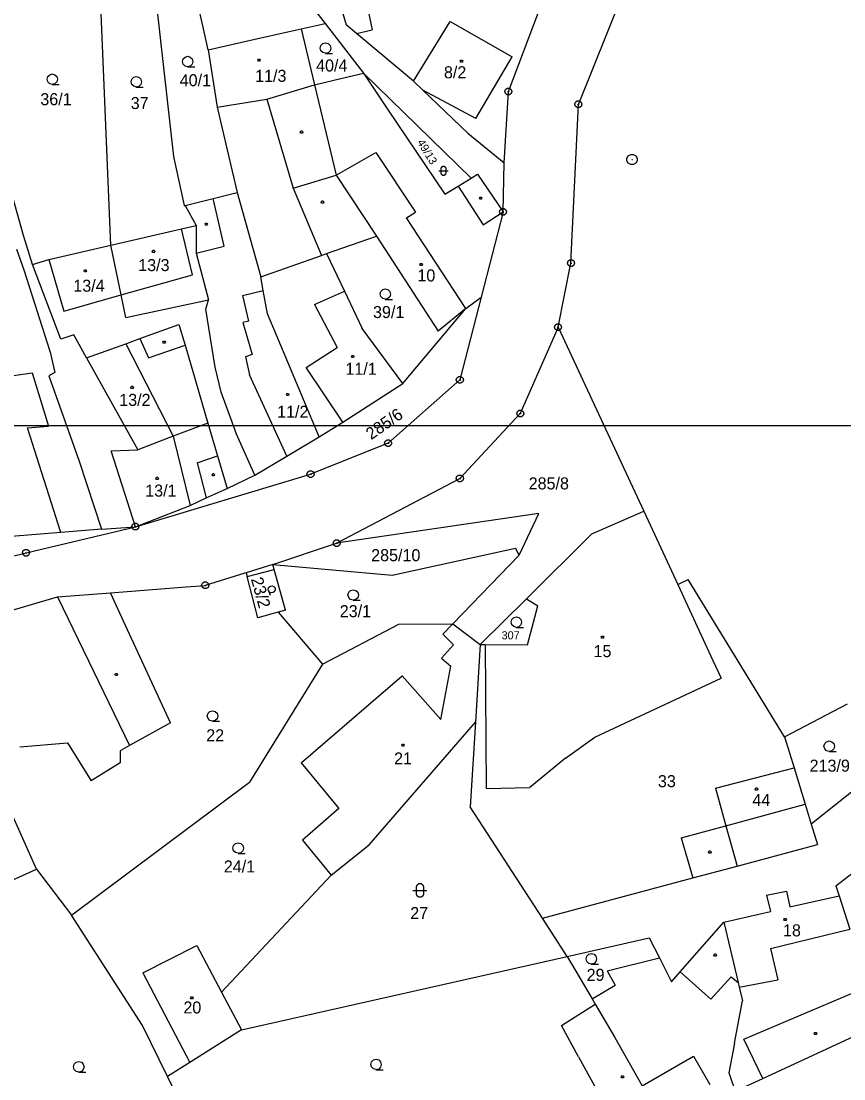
# Model space of a CAD drawing. Extents: x -780000 to -777378, y -1011169 to -1009297.
# Drawn here: x -779102.6 to -778986.4, y -1010360.1 to -1010210.7 of the extents above; entities that cross this region are included whole.
import ezdxf

# ---------------------------------------------------------------- set-up
doc = ezdxf.new("R2010")
doc.units = 0
for name, color, linetype in [('Default', 7, 'Continuous'), ('KN_HRANICE', 7, 'Continuous'), ('KN_KULTURY', 7, 'Continuous'), ('KN_PARCELY', 7, 'Continuous'), ('KN_SLUCKY', 7, 'Continuous'), ('LEGENDA', 7, 'Continuous')]:
    doc.layers.add(name, color=color, linetype=linetype)

# ---------------------------------------------------------------- blocks, each defined once
blk = doc.blocks.new('101')
at = {"layer": 'Default'}
blk.add_line((-0.05, 0), (0.05, 0), dxfattribs=at)
blk.add_lwpolyline([(0.19, 0.72), (0.53, 0.53), (0.72, 0.19), (0.72, -0.2), (0.53, -0.54), (0.19, -0.73), (-0.2, -0.73), (-0.54, -0.54), (-0.73, -0.2), (-0.73, 0.19), (-0.54, 0.53), (-0.2, 0.72), (0.19, 0.72)], dxfattribs=at)
blk = doc.blocks.new('304')
at = {"layer": 'Default'}
blk.add_lwpolyline([(0, 0), (-0.38, 0.1), (-0.65, 0.37), (-0.75, 0.74), (-0.65, 1.11), (-0.38, 1.38), (-0.01, 1.48), (0.36, 1.38), (0.63, 1.11), (0.73, 0.73), (0.63, 0.35), (0.36, 0.08), (-0.02, -0.02), (0.98, -0.02)], dxfattribs=at)
blk = doc.blocks.new('316')
at = {"layer": 'Default'}
for points in [[(-0.5, 1.5), (-0.4, 1.79), (-0.15, 1.97), (0.16, 1.97), (0.41, 1.79), (0.51, 1.5), (0.51, 0.5), (0.41, 0.21), (0.16, 0.03), (-0.15, 0.03), (-0.4, 0.21), (-0.5, 0.5), (-0.5, 1.5)], [(-1, 1), (0.27, 1), (1, 1)]]:
    blk.add_lwpolyline(points, dxfattribs=at)
blk = doc.blocks.new('NAHRADNI_SYMBOL')
at = {"layer": 'Default'}
blk.add_lwpolyline([(0.09, 0.15), (0.18, 0), (0.09, -0.15), (-0.09, -0.15), (-0.18, 0), (-0.09, 0.15), (0.09, 0.15)], dxfattribs=at)
blk = doc.blocks.new('402')
at = {"layer": 'Default'}
blk.add_lwpolyline([(0.09, 0.15), (0.18, 0), (0.09, -0.15), (-0.09, -0.15), (-0.18, 0), (-0.09, 0.15), (0.09, 0.15)], dxfattribs=at)
blk = doc.blocks.new('105')
at = {"layer": 'Default'}
blk.add_line((-0.12, 0), (0.12, 0), dxfattribs=at)
blk.add_lwpolyline([(0.15, 0.48), (0.4, 0.3), (0.5, 0.01), (0.4, -0.28), (0.15, -0.46), (-0.16, -0.46), (-0.41, -0.28), (-0.51, 0.01), (-0.41, 0.3), (-0.16, 0.48), (0.15, 0.48)], dxfattribs=at)

msp = doc.modelspace()

# ---------------------------------------------------------------- linework, layer by layer
at = {"layer": 'KN_HRANICE'}
for p, q in [((-779089.99, -1010242.37), (-779091.64, -1010201.91)), ((-779076.2, -1010214.76), (-779078.76, -1010203.29)), ((-779023.92, -1010222.47), (-779017.34, -1010206.13)), ((-779062.19, -1010207.85), (-779059.7, -1010211.07)), ((-779057.43, -1010208.85), (-779056.71, -1010211.24)), ((-779033.8, -1010220.65), (-779029.4, -1010209.06)), ((-779069.82, -1010213.33), (-779064.77, -1010212.2)), ((-779064.77, -1010212.2), (-779063.08, -1010211.82)), ((-779063.08, -1010211.82), (-779059.7, -1010211.07)), ((-779063.08, -1010211.82), (-779061.2, -1010219.69)), ((-779059.7, -1010211.07), (-779054.29, -1010218.08)), ((-779055.26, -1010212.45), (-779056.71, -1010211.24)), ((-779076.2, -1010214.76), (-779069.82, -1010213.33)), ((-779047.2, -1010219.18), (-779055.26, -1010212.45)), ((-779076.2, -1010214.76), (-779074.94, -1010222.88)), ((-779057.29, -1010218.78), (-779054.29, -1010218.08)), ((-779054.29, -1010218.08), (-779050.87, -1010223.15)), ((-779054.29, -1010218.08), (-779039.06, -1010232.9)), ((-779061.2, -1010219.69), (-779057.29, -1010218.78)), ((-779061.2, -1010219.69), (-779058.14, -1010232.46)), ((-779047.2, -1010219.18), (-779045.87, -1010220.45)), ((-779045.87, -1010220.45), (-779039.55, -1010226.53)), ((-779034.42, -1010230.71), (-779033.8, -1010220.65)), ((-779024.96, -1010244.9), (-779023.92, -1010222.47)), ((-779074.94, -1010222.88), (-779072.13, -1010234.9)), ((-779050.87, -1010223.15), (-779042.77, -1010235.17)), ((-779039.55, -1010226.53), (-779034.42, -1010230.71)), ((-779102.33, -1010241), (-779105.07, -1010231.05)), ((-779034.55, -1010237.65), (-779034.42, -1010230.71)), ((-779058.14, -1010232.46), (-779052.46, -1010241.08)), ((-779040.92, -1010234.04), (-779039.06, -1010232.9)), ((-779039.06, -1010232.9), (-779038.16, -1010232.35)), ((-779038.16, -1010232.35), (-779034.55, -1010237.65)), ((-779042.77, -1010235.17), (-779040.92, -1010234.04)), ((-779079.48, -1010236.74), (-779075.52, -1010235.75)), ((-779075.52, -1010235.75), (-779072.13, -1010234.9)), ((-779072.13, -1010234.9), (-779068.8, -1010246.85)), ((-779079.62, -1010236.77), (-779079.48, -1010236.74)), ((-779079.48, -1010236.74), (-779077.92, -1010239.59)), ((-779034.55, -1010237.65), (-779037.66, -1010249.73)), ((-779089.99, -1010242.37), (-779079.97, -1010240.06)), ((-779079.97, -1010240.06), (-779077.92, -1010239.59)), ((-779077.92, -1010239.59), (-779077.92, -1010243.48)), ((-779101.02, -1010245.11), (-779102.33, -1010241)), ((-779059.5, -1010243.56), (-779052.46, -1010241.08)), ((-779052.46, -1010241.08), (-779043.73, -1010254.53)), ((-779103.32, -1010242.93), (-779102.28, -1010245.85)), ((-779098.71, -1010244.39), (-779089.99, -1010242.37)), ((-779088.5, -1010249.4), (-779089.99, -1010242.37)), ((-779077.92, -1010243.48), (-779076.18, -1010250.09)), ((-779060.22, -1010243.82), (-779059.5, -1010243.56)), ((-779059.5, -1010243.56), (-779056.98, -1010248.86)), ((-779101.02, -1010245.11), (-779098.71, -1010244.39)), ((-779097.05, -1010255.65), (-779101.02, -1010245.11)), ((-779068.8, -1010246.85), (-779060.22, -1010243.82)), ((-779026.78, -1010253.95), (-779024.96, -1010244.9)), ((-779102.28, -1010245.85), (-779098.52, -1010257.5)), ((-779068.44, -1010248.79), (-779068.8, -1010246.85)), ((-779087.83, -1010252.59), (-779088.5, -1010249.4)), ((-779067.83, -1010252.08), (-779068.44, -1010248.79)), ((-779056.98, -1010248.86), (-779054.48, -1010254.13)), ((-779037.66, -1010249.73), (-779040.66, -1010261.41)), ((-779039.84, -1010251.3), (-779037.66, -1010249.73)), ((-779087.83, -1010252.59), (-779076.18, -1010250.09)), ((-779076.54, -1010251.4), (-779076.18, -1010250.09)), ((-779075.23, -1010259.6), (-779076.54, -1010251.4)), ((-779066.56, -1010255.1), (-779067.83, -1010252.08)), ((-779048.74, -1010261.92), (-779039.84, -1010251.3)), ((-779039.84, -1010251.3), (-779043.73, -1010254.53)), ((-779085.85, -1010255.56), (-779080.36, -1010253.56)), ((-779080.36, -1010253.56), (-779079.49, -1010256.51)), ((-779048.74, -1010261.92), (-779054.48, -1010254.13)), ((-779026.78, -1010253.95), (-779032.12, -1010266.16)), ((-779026.78, -1010253.95), (-779014.69, -1010279.95)), ((-779095.21, -1010255.03), (-779097.05, -1010255.65)), ((-779093.41, -1010258.3), (-779095.21, -1010255.03)), ((-779087.87, -1010256.29), (-779085.85, -1010255.56)), ((-779060.55, -1010269.44), (-779066.56, -1010255.1)), ((-779093.41, -1010258.3), (-779087.87, -1010256.29)), ((-779079.49, -1010256.51), (-779076.26, -1010267.51)), ((-779098.52, -1010257.5), (-779097.87, -1010260.36)), ((-779093.41, -1010258.3), (-779086.17, -1010271.27)), ((-779107.93, -1010261.36), (-779101.09, -1010260.41)), ((-779101.09, -1010260.41), (-779098.76, -1010267.92)), ((-779097.87, -1010260.36), (-779098.72, -1010260.84)), ((-779098.72, -1010260.84), (-779094.46, -1010272.88)), ((-779050.79, -1010270.34), (-779040.66, -1010261.41)), ((-779057.2, -1010267.35), (-779048.74, -1010261.92)), ((-779032.12, -1010266.16), (-779040.66, -1010275.32)), ((-779076.26, -1010267.51), (-779081.16, -1010269.37)), ((-779076.26, -1010267.51), (-779074.9, -1010272.13)), ((-779060.55, -1010269.44), (-779057.2, -1010267.35)), ((-779101.73, -1010268.16), (-779098.76, -1010267.92)), ((-779097.04, -1010282.96), (-779101.73, -1010268.16)), ((-779081.16, -1010269.37), (-779086.17, -1010271.27)), ((-779065.1, -1010272.18), (-779060.55, -1010269.44)), ((-779050.79, -1010270.34), (-779061.75, -1010274.71)), ((-779089.91, -1010271.43), (-779086.17, -1010271.27)), ((-779086.5, -1010282.14), (-779089.91, -1010271.43)), ((-779074.9, -1010272.13), (-779073.55, -1010276.72)), ((-779094.46, -1010272.88), (-779091.27, -1010282.5)), ((-779069.64, -1010274.85), (-779065.1, -1010272.18)), ((-779086.5, -1010282.14), (-779061.75, -1010274.71)), ((-779073.55, -1010276.72), (-779069.64, -1010274.85)), ((-779058.07, -1010284.48), (-779040.66, -1010275.32)), ((-779078.75, -1010279.13), (-779076.48, -1010278.07)), ((-779076.48, -1010278.07), (-779073.55, -1010276.72)), ((-779086.5, -1010282.14), (-779078.75, -1010279.13)), ((-779029.51, -1010280.26), (-779058.07, -1010284.48)), ((-779032.26, -1010286.16), (-779029.51, -1010280.26)), ((-779022.02, -1010283.13), (-779014.69, -1010279.95)), ((-779014.69, -1010279.95), (-779009.89, -1010290.29)), ((-779101.94, -1010285.82), (-779086.5, -1010282.14)), ((-779091.27, -1010282.5), (-779097.04, -1010282.96)), ((-779091.27, -1010282.5), (-779086.5, -1010282.14)), ((-779022.02, -1010283.13), (-779031.26, -1010292.31)), ((-779067.08, -1010287.5), (-779058.07, -1010284.48)), ((-779050.21, -1010289), (-779032.82, -1010285.16)), ((-779032.26, -1010286.16), (-779032.82, -1010285.16)), ((-779112.94, -1010288.54), (-779101.94, -1010285.82)), ((-779041.67, -1010295.86), (-779032.26, -1010286.16)), ((-779067.08, -1010287.5), (-779070.83, -1010288.65)), ((-779066.89, -1010288.17), (-779067.08, -1010287.5)), ((-779067.08, -1010287.5), (-779050.21, -1010289)), ((-779065.31, -1010293.92), (-779066.89, -1010288.17)), ((-779071.05, -1010288.72), (-779076.63, -1010290.43)), ((-779070.83, -1010288.65), (-779071.05, -1010288.72)), ((-779070.83, -1010288.65), (-779070.69, -1010289.16)), ((-779069.19, -1010295.01), (-779070.69, -1010289.16)), ((-779009.89, -1010290.29), (-779008.43, -1010289.59)), ((-778994.79, -1010311.83), (-779008.43, -1010289.59)), ((-779097.5, -1010292.06), (-779090.04, -1010291.48)), ((-779090.04, -1010291.48), (-779079.33, -1010290.64)), ((-779087.9, -1010296.09), (-779090.04, -1010291.48)), ((-779079.33, -1010290.64), (-779076.63, -1010290.43)), ((-779009.89, -1010290.29), (-779004.9, -1010301.02)), ((-779107.13, -1010294.85), (-779097.5, -1010292.06)), ((-779031.26, -1010292.31), (-779037.78, -1010298.79)), ((-779031.26, -1010292.31), (-779029.63, -1010293.31)), ((-779066.34, -1010294.21), (-779069.19, -1010295.01)), ((-779065.31, -1010293.92), (-779066.34, -1010294.21)), ((-779066.34, -1010294.21), (-779060.06, -1010301.54)), ((-779031.09, -1010298.84), (-779029.63, -1010293.31)), ((-779060.06, -1010301.54), (-779049.3, -1010295.9)), ((-779049.3, -1010295.9), (-779041.67, -1010295.86)), ((-779043.09, -1010297.32), (-779041.67, -1010295.86)), ((-779041.67, -1010295.86), (-779037.78, -1010298.79)), ((-779081.53, -1010309.87), (-779087.9, -1010296.09)), ((-779043.09, -1010297.32), (-779041.55, -1010298.82)), ((-779043.27, -1010300.7), (-779041.55, -1010298.82)), ((-779037.78, -1010298.79), (-779038.46, -1010309.75)), ((-779037.78, -1010298.79), (-779037.1, -1010298.8)), ((-779037.1, -1010298.8), (-779031.09, -1010298.84)), ((-779037.1, -1010298.8), (-779036.94, -1010319.12)), ((-779060.06, -1010301.54), (-779070.4, -1010318.23)), ((-779043.36, -1010309.37), (-779041.95, -1010301.84)), ((-779043.27, -1010300.7), (-779041.95, -1010301.84)), ((-779004.9, -1010301.02), (-779003.74, -1010303.52)), ((-779063.1, -1010315.51), (-779048.83, -1010303.23)), ((-779043.36, -1010309.37), (-779048.83, -1010303.23)), ((-779021.61, -1010311.89), (-779003.74, -1010303.52)), ((-778994.79, -1010311.83), (-778985.9, -1010307.16)), ((-779081.53, -1010309.87), (-779087.34, -1010313.07)), ((-779053.49, -1010327.09), (-779038.46, -1010309.75)), ((-779038.46, -1010309.75), (-779039.2, -1010321.7)), ((-779025.76, -1010314.84), (-779021.61, -1010311.89)), ((-778994.79, -1010311.83), (-778993.45, -1010316.22)), ((-779102.83, -1010313.22), (-779096.1, -1010312.69)), ((-779096.1, -1010312.69), (-779092.74, -1010318.04)), ((-779087.34, -1010313.07), (-779088.67, -1010313.8)), ((-779088.67, -1010313.8), (-779088.64, -1010315.52)), ((-779025.76, -1010314.84), (-779030.77, -1010318.99)), ((-779088.64, -1010315.52), (-779092.74, -1010318.04)), ((-779063.1, -1010315.51), (-779057.77, -1010321.93)), ((-779004.53, -1010319.08), (-778993.45, -1010316.22)), ((-778993.45, -1010316.22), (-778991.89, -1010321.33)), ((-779095.54, -1010337.04), (-779070.4, -1010318.23)), ((-778982.17, -1010317.08), (-778991.02, -1010324.17)), ((-779036.94, -1010319.12), (-779030.77, -1010318.99)), ((-779004.53, -1010319.08), (-779003.07, -1010324.38)), ((-778991.89, -1010321.33), (-778991.02, -1010324.17)), ((-779100.48, -1010330.51), (-779104.32, -1010321.87)), ((-779057.77, -1010321.93), (-779062.91, -1010326.41)), ((-779028.99, -1010337.46), (-779039.2, -1010321.7)), ((-779009.39, -1010326.11), (-779003.07, -1010324.38)), ((-778991.02, -1010324.17), (-778990.15, -1010327.02)), ((-779062.91, -1010326.41), (-779058.85, -1010331.38)), ((-779058.85, -1010331.38), (-779053.49, -1010327.09)), ((-779009.39, -1010326.11), (-779007.73, -1010331.75)), ((-779001.5, -1010330.08), (-778990.15, -1010327.02)), ((-779007.73, -1010331.75), (-779001.5, -1010330.08)), ((-778987.54, -1010332.88), (-778983.88, -1010330.06)), ((-779108.53, -1010334.17), (-779100.48, -1010330.51)), ((-779100.48, -1010330.51), (-779095.54, -1010337.04)), ((-779058.85, -1010331.38), (-779074.32, -1010347.9)), ((-779028.99, -1010337.46), (-779007.73, -1010331.75)), ((-778987.54, -1010332.88), (-778987.09, -1010334.27)), ((-778997.34, -1010334.21), (-778994.52, -1010333.62)), ((-778997.34, -1010334.21), (-778996.76, -1010336.48)), ((-778994.52, -1010333.62), (-778994.02, -1010335.85)), ((-778994.02, -1010335.85), (-778987.09, -1010334.27)), ((-779085.48, -1010352.6), (-779095.54, -1010337.04)), ((-779025.5, -1010342.84), (-779028.99, -1010337.46)), ((-779003.36, -1010337.99), (-778996.76, -1010336.48)), ((-779006.8, -1010341.91), (-779003.36, -1010337.99)), ((-779003.36, -1010337.99), (-779001.36, -1010346.54)), ((-779025.5, -1010342.84), (-779013.91, -1010340.22)), ((-779013.91, -1010340.22), (-779012.47, -1010343.06)), ((-779085.43, -1010345.18), (-779077.83, -1010341.29)), ((-779077.83, -1010341.29), (-779074.32, -1010347.9)), ((-779009.52, -1010345.02), (-779006.8, -1010341.91)), ((-779071.49, -1010353.21), (-779025.5, -1010342.84)), ((-779025.5, -1010342.84), (-779021.98, -1010348.86)), ((-779019.86, -1010344.89), (-779012.47, -1010343.06)), ((-779012.47, -1010343.06), (-779010.76, -1010346.43)), ((-779085.43, -1010345.18), (-779078.82, -1010357.83)), ((-779019.86, -1010344.89), (-779018.7, -1010346.92)), ((-779010.76, -1010346.43), (-779009.52, -1010345.02)), ((-779001.36, -1010346.54), (-779001.2, -1010347.2)), ((-779074.32, -1010347.9), (-779071.49, -1010353.21)), ((-779021.98, -1010348.86), (-779018.7, -1010346.92)), ((-779001.2, -1010347.2), (-779000.74, -1010349.14)), ((-779026.3, -1010352.61), (-779021.56, -1010349.58)), ((-779021.98, -1010348.86), (-779021.56, -1010349.58)), ((-779001.87, -1010355.1), (-779000.74, -1010349.14)), ((-779081.96, -1010359.81), (-779085.48, -1010352.6)), ((-779023.89, -1010357.02), (-779026.3, -1010352.61)), ((-778997.87, -1010360.08), (-778982.04, -1010352.73)), ((-779071.49, -1010353.21), (-779078.82, -1010357.83)), ((-779001.87, -1010355.1), (-779002.67, -1010359.29)), ((-779023.89, -1010357.02), (-779017.69, -1010368.36)), ((-779078.82, -1010357.83), (-779081.96, -1010359.81)), ((-779071.95, -1010380.31), (-779081.96, -1010359.81)), ((-779002.67, -1010359.29), (-779002.49, -1010359.8)), ((-779002.49, -1010359.8), (-779001.76, -1010361.88)), ((-779001.76, -1010361.88), (-778997.87, -1010360.08))]:
    msp.add_line(p, q, dxfattribs=at)
for points in [[(-779084.45, -1010200.01), (-779081.11, -1010229.82), (-779079.62, -1010236.77)], [(-779069.64, -1010274.85), (-779072.2, -1010269.07), (-779072.39, -1010268.55), (-779072.64, -1010267.9), (-779074.39, -1010263.13), (-779075.23, -1010259.6)], [(-779097.04, -1010282.96), (-779103.42, -1010283.46), (-779104.11, -1010283.52), (-779106.44, -1010283.7)]]:
    msp.add_lwpolyline(points, dxfattribs=at)
at = {"layer": 'KN_SLUCKY'}
for p, q in [((-779053.86, -1010208.15), (-779053.04, -1010211.92)), ((-779047.2, -1010219.18), (-779042.03, -1010210.78)), ((-779042.03, -1010210.78), (-779033.28, -1010215.75)), ((-779055.26, -1010212.45), (-779053.04, -1010211.92)), ((-779038.39, -1010224.47), (-779033.28, -1010215.75)), ((-779067.91, -1010221.73), (-779061.2, -1010219.69)), ((-779038.39, -1010224.47), (-779045.87, -1010220.45)), ((-779074.94, -1010222.88), (-779067.91, -1010221.73)), ((-779067.91, -1010221.73), (-779064.23, -1010234.32)), ((-779058.14, -1010232.46), (-779052.52, -1010229.28)), ((-779052.52, -1010229.28), (-779046.93, -1010237.71)), ((-779064.23, -1010234.32), (-779058.14, -1010232.46)), ((-779064.23, -1010234.32), (-779060.22, -1010243.82)), ((-779040.92, -1010234.04), (-779037.38, -1010239.5)), ((-779048.2, -1010238.48), (-779046.93, -1010237.71)), ((-779037.38, -1010239.5), (-779034.55, -1010237.65)), ((-779039.84, -1010251.3), (-779048.2, -1010238.48)), ((-779078.41, -1010246.55), (-779079.97, -1010240.06)), ((-779098.71, -1010244.39), (-779096.62, -1010251.69)), ((-779088.5, -1010249.4), (-779078.41, -1010246.55)), ((-779096.62, -1010251.69), (-779088.5, -1010249.4)), ((-779071.35, -1010249.46), (-779068.44, -1010248.79)), ((-779061.2, -1010250.75), (-779056.98, -1010248.86)), ((-779061.2, -1010250.75), (-779057.98, -1010256.83)), ((-779085.85, -1010255.56), (-779084.65, -1010258.28)), ((-779087.87, -1010256.29), (-779081.16, -1010269.37)), ((-779084.65, -1010258.28), (-779079.49, -1010256.51)), ((-779062.39, -1010259.63), (-779057.98, -1010256.83)), ((-779057.2, -1010267.35), (-779062.39, -1010259.63)), ((-779065.1, -1010272.18), (-779070.38, -1010260.68)), ((-779081.16, -1010269.37), (-779078.75, -1010279.13)), ((-779077.79, -1010273.1), (-779074.9, -1010272.13)), ((-779077.79, -1010273.1), (-779076.48, -1010278.07)), ((-779070.69, -1010289.16), (-779066.89, -1010288.17)), ((-779097.5, -1010292.06), (-779087.34, -1010313.07)), ((-779003.07, -1010324.38), (-778991.89, -1010321.33)), ((-779003.07, -1010324.38), (-779001.5, -1010330.08)), ((-778987.09, -1010334.27), (-778985.56, -1010339)), ((-778996.79, -1010341.72), (-778985.56, -1010339)), ((-778996.79, -1010341.72), (-778995.73, -1010346.15)), ((-779009.52, -1010345.02), (-779005.2, -1010348.89)), ((-779005.2, -1010348.89), (-779002.31, -1010345.73)), ((-779002.31, -1010345.73), (-779001.36, -1010346.54)), ((-779001.2, -1010347.2), (-778995.73, -1010346.15)), ((-779000.55, -1010354.53), (-778983.47, -1010347.31)), ((-779021.56, -1010349.58), (-779018.79, -1010354.32)), ((-779018.79, -1010354.32), (-779014.92, -1010361.14)), ((-778997.87, -1010360.08), (-779000.55, -1010354.53)), ((-779014.92, -1010361.14), (-779007.64, -1010356.95)), ((-779007.64, -1010356.95), (-779005.36, -1010360.92))]:
    msp.add_line(p, q, dxfattribs=at)
for points in [[(-779077.92, -1010243.48), (-779073.96, -1010242.51), (-779075.52, -1010235.75)], [(-779071.35, -1010249.46), (-779070.54, -1010253.09), (-779071.3, -1010253.31), (-779070, -1010257.83), (-779070.95, -1010258.14), (-779070.38, -1010260.68)]]:
    msp.add_lwpolyline(points, dxfattribs=at)
at = {"layer": 'LEGENDA'}
msp.add_lwpolyline([(-779530.66, -1010687.91), (-778936.66, -1010687.91), (-778936.66, -1010267.91), (-779530.66, -1010267.91)], close=True, dxfattribs=at)

# ---------------------------------------------------------------- block references
at = {"layer": 'KN_KULTURY'}
for name, p in [('304', (-779059.63, -1010215.26)), ('304', (-779079.1, -1010217.16)), ('402', (-779069.04, -1010216.22)), ('402', (-779040.44, -1010216.37)), ('304', (-779098.23, -1010219.66)), ('304', (-779086.36, -1010220.02)), ('402', (-779063.03, -1010226.38)), ('402', (-779060.07, -1010236.27)), ('402', (-779037.72, -1010235.71)), ('402', (-779076.48, -1010239.41)), ('402', (-779083.93, -1010243.24)), ('402', (-779046.12, -1010245.08)), ('402', (-779093.58, -1010245.99)), ('304', (-779051.18, -1010250)), ('402', (-779082.45, -1010256.08)), ('402', (-779055.8, -1010258.09)), ('402', (-779086.97, -1010262.45)), ('402', (-779064.98, -1010263.45)), ('402', (-779075.49, -1010274.79)), ('402', (-779083.41, -1010275.31)), ('304', (-779055.72, -1010292.52)), ('304', (-779032.67, -1010296.36)), ('NAHRADNI_SYMBOL', (-779020.51, -1010297.75)), ('402', (-779089.2, -1010303.01)), ('304', (-779075.59, -1010309.61)), ('304', (-778988.47, -1010313.89)), ('NAHRADNI_SYMBOL', (-779048.69, -1010313)), ('402', (-778998.76, -1010319.2)), ('304', (-779071.97, -1010328.28)), ('402', (-779005.34, -1010328.1)), ('316', (-779046.31, -1010334.53)), ('402', (-778994.69, -1010337.62)), ('304', (-779022.07, -1010343.93)), ('402', (-779004.6, -1010342.65)), ('402', (-779078.54, -1010348.71)), ('402', (-778990.42, -1010353.75)), ('304', (-779094.49, -1010359.19)), ('304', (-779052.49, -1010358.84)), ('402', (-779017.68, -1010359.85))]:
    msp.add_blockref(name, p, dxfattribs=at)
at = {"layer": 'KN_KULTURY', "xscale": 0.67, "yscale": 0.67}
msp.add_blockref('316', (-779042.98, -1010232.52), dxfattribs=at)
at = {"layer": 'KN_KULTURY', "xscale": 0.67, "yscale": 0.6699999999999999, "rotation": -67.61963700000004}
msp.add_blockref('304', (-779067.69, -1010291.18), dxfattribs=at)
at = {"layer": 'KN_PARCELY'}
for name, p in [('105', (-779033.8, -1010220.65)), ('105', (-779023.92, -1010222.47)), ('101', (-779016.33, -1010230.26)), ('105', (-779034.55, -1010237.65)), ('105', (-779024.96, -1010244.9)), ('105', (-779026.78, -1010253.95)), ('105', (-779040.66, -1010261.41)), ('105', (-779032.12, -1010266.16)), ('105', (-779050.79, -1010270.34)), ('105', (-779061.75, -1010274.71)), ('105', (-779040.66, -1010275.32)), ('105', (-779086.5, -1010282.14)), ('105', (-779058.07, -1010284.48)), ('105', (-779101.94, -1010285.82)), ('105', (-779076.63, -1010290.43))]:
    msp.add_blockref(name, p, dxfattribs=at)

# ---------------------------------------------------------------- texts
for s, height, p in [('40/4', 1.7, (-779060.97, -1010217.83)), ('40/1', 1.7, (-779080.24, -1010219.91)), ('11/3', 1.7, (-779069.59, -1010219.29)), ('8/2', 1.7, (-779042.91, -1010218.79)), ('36/1', 1.7, (-779099.93, -1010222.59)), ('37', 1.7, (-779087.16, -1010223.13)), ('13/3', 1.7, (-779086.1, -1010246.03)), ('10', 1.7, (-779046.66, -1010247.49)), ('13/4', 1.7, (-779095.27, -1010248.94)), ('39/1', 1.7, (-779052.93, -1010252.66)), ('11/1', 1.7, (-779056.83, -1010260.68)), ('13/2', 1.7, (-779088.78, -1010265.07)), ('11/2', 1.7, (-779066.48, -1010266.75)), ('285/8', 1.7, (-779030.94, -1010276.87)), ('13/1', 1.7, (-779085.11, -1010277.89)), ('285/10', 1.7, (-779053.19, -1010287.01)), ('23/1', 1.7, (-779057.63, -1010294.92)), ('307', 1.14, (-779034.76, -1010298.05)), ('15', 1.7, (-779021.77, -1010300.57)), ('22', 1.7, (-779076.49, -1010312.46)), ('21', 1.7, (-779049.96, -1010315.73)), ('213/9', 1.7, (-778991.25, -1010316.75)), ('33', 1.7, (-779012.68, -1010318.94)), ('44', 1.7, (-778999.34, -1010321.61)), ('24/1', 1.7, (-779074.01, -1010330.99)), ('27', 1.7, (-779047.67, -1010337.58)), ('18', 1.7, (-778995.01, -1010340.02)), ('29', 1.7, (-779022.75, -1010346.3)), ('20', 1.7, (-779079.72, -1010350.91))]:
    msp.add_text(s, height=height, dxfattribs=at).set_placement(p)
for s, height, rotation, p in [('49/13', 1.14, 301.261, (-779046.74, -1010227.83)), ('285/6', 1.7, 35.008, (-779053.19, -1010269.93)), ('23/2', 1.7, 285.448, (-779070.19, -1010289.53))]:
    msp.add_text(s, height=height, rotation=rotation, dxfattribs=at).set_placement(p)

doc.saveas('drawing.dxf')
